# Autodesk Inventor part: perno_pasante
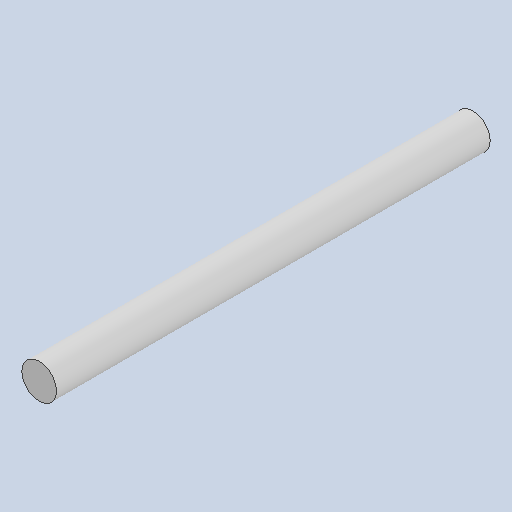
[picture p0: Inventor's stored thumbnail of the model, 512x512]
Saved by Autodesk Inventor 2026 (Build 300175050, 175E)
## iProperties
Created: 2025-06
Part Number: perno_pasante
Material: Genérico
Document SubType Name: Modeling
Designer: piero
Density: 1 g/cm^3
Appearance: Valor por defecto
Author: piero
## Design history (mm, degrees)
sketch "Boceto1"
  geometry: C1 r 4 at (0, 0); 1 further point
  constraints: 1 centre point, 1 coincident
  dimensions: "d0" = 8 diameter of C1
extrude "Extrusión1" new body sketch "Boceto1" distance "d1" = 100; taper "d2" = 0 deg
node "Sólido1"
